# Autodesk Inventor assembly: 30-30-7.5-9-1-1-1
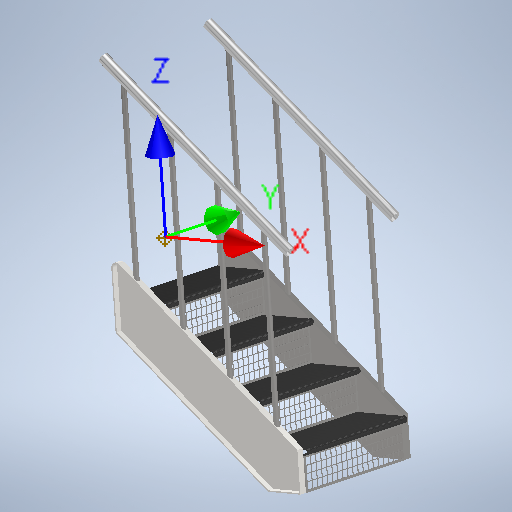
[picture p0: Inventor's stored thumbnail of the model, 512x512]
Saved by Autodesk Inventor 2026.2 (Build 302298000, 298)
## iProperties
RuleStatus: InUse
Company: Elevation Stair Company
AfterAnyUserParamChange0: Type Name
Created: 2026-01
Part Number: 30-30-7.5-9-1-1-1
Description: Metal Stairs
Document SubType Name: Assembly
Designer: MichelleRasmussen
Run: 9.000 in
TheAngle: 39.81 deg
TargetRise: 7.250 in
Rise: 7.500 in
Height: 30.000 in
Width: 30.000 in
StringerWidth: 10.000 in
StringerThickness: 1.500 in
StringerLength: 46.861 in
NumberOfSteps: 5.000 ul
Length: 36.000 in
TreadThickness: 1.250 in
StringerStockLength: 48.000 in
RailingStockLength: 46.861 in
RailingWidth: 3.000 in
RailingThickness: 2.000 in
RightRail: True
LeftRail: True
StringerMaterial: Steel, Galvanized
TreadMaterial: Steel, Wrought
RiserMaterial: Steel, Galvanized
BalusterMaterial: Steel, Galvanized
HandrailMaterial: Aluminum 6061
HasHandrail: True
HasRiser: True
BalusterLength: 36.000 in
BalusterDia: 1.000 in
INDDataset: sample
Author: MichelleRasmussen
Created: 2022-06
Designer: David Reaume
Author: David Reaume
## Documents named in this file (8)
- C:\Users\MichelleRasmussen\OneDrive\Documents\AutodeskTraining\Autodesk\Informed Design\Staircase Sample1\Staircase Sample\Staircase Sample.iam
- C:\Users\MichelleRasmussen\OneDrive\Documents\AutodeskTraining\Autodesk\Informed Design\Staircase Sample1\Staircase Sample\Stringer.ipt
- C:\Users\MichelleRasmussen\OneDrive\Documents\AutodeskTraining\Autodesk\Informed Design\Staircase Sample1\Staircase Sample\Tread.ipt
- C:\Users\MichelleRasmussen\OneDrive\Documents\AutodeskTraining\Autodesk\Informed Design\Staircase Sample1\Staircase Sample\Riser.ipt
- C:\Users\MichelleRasmussen\OneDrive\Documents\AutodeskTraining\Autodesk\Informed Design\Staircase Sample1\Staircase Sample\Baluster.ipt
- C:\Users\MichelleRasmussen\OneDrive\Documents\AutodeskTraining\Autodesk\Informed Design\Staircase Sample1\Staircase Sample\Railing.ipt
- C:\Users\MichelleRasmussen\OneDrive\Documents\AutodeskTraining\Autodesk\Informed Design\Staircase Sample1\Staircase Sample\Left Stringer_MIR.ipt
- C:\Users\MichelleRasmussen\OneDrive\Documents\AutodeskTraining\Autodesk\Informed Design\Staircase Sample1\Staircase Sample\Staircase Sample_Simplify_1.ipt
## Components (20 placed, 7 different names)
1. Stringer
2. Left Stringer_MIR:1 — Mate:2
3. Right Railing
4. Left Railing — Flush:7, Flush:8, Flush:9
5. Tread:1 — Mate:1
6. Tread:2
7. Tread:3
8. Tread:4
9. Riser:1
10. Riser:2
11. Riser:3
12. Riser:4
13. Baluster:1
14. Baluster:12
15. Baluster:15
16. Baluster:17
17. Baluster:7 — Flush:11, Flush:12
18. Baluster:8
19. Baluster:13
20. Baluster:16
## Component patterns: Tread Pattern (4 elements), Riser Pattern (4 elements), Right Baluster Pattern (4 elements), Left Baluster Pattern (4 elements)
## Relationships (7: Flush 5, Mate 2)
- Flush:7: Left Railing
- Flush:8: Left Railing
- Flush:9: Left Railing
- Flush:11: Baluster:7
- Flush:12: Baluster:7
- Mate:1: Tread:1
- Mate:2: Left Stringer_MIR:1
## Named parameters: TheAngle = 6.94738 mm, StringerThickness = 38.1 mm, StringerLength = 1190.28205 mm, Length = 914.4 mm, TheAngleRounded = 6.94816 mm, StringerStockLength = 1219.2 mm, DiagonalTreadSpacing = 297.57051 mm, BalusterDia = 25.4 mm, BalusterLength = 914.4 mm, RailingStockLength = 1190.28205 mm, RailingWidth = 76.2 mm, RailingThickness = 50.8 mm, StringerSpacing = 876.3 mm
